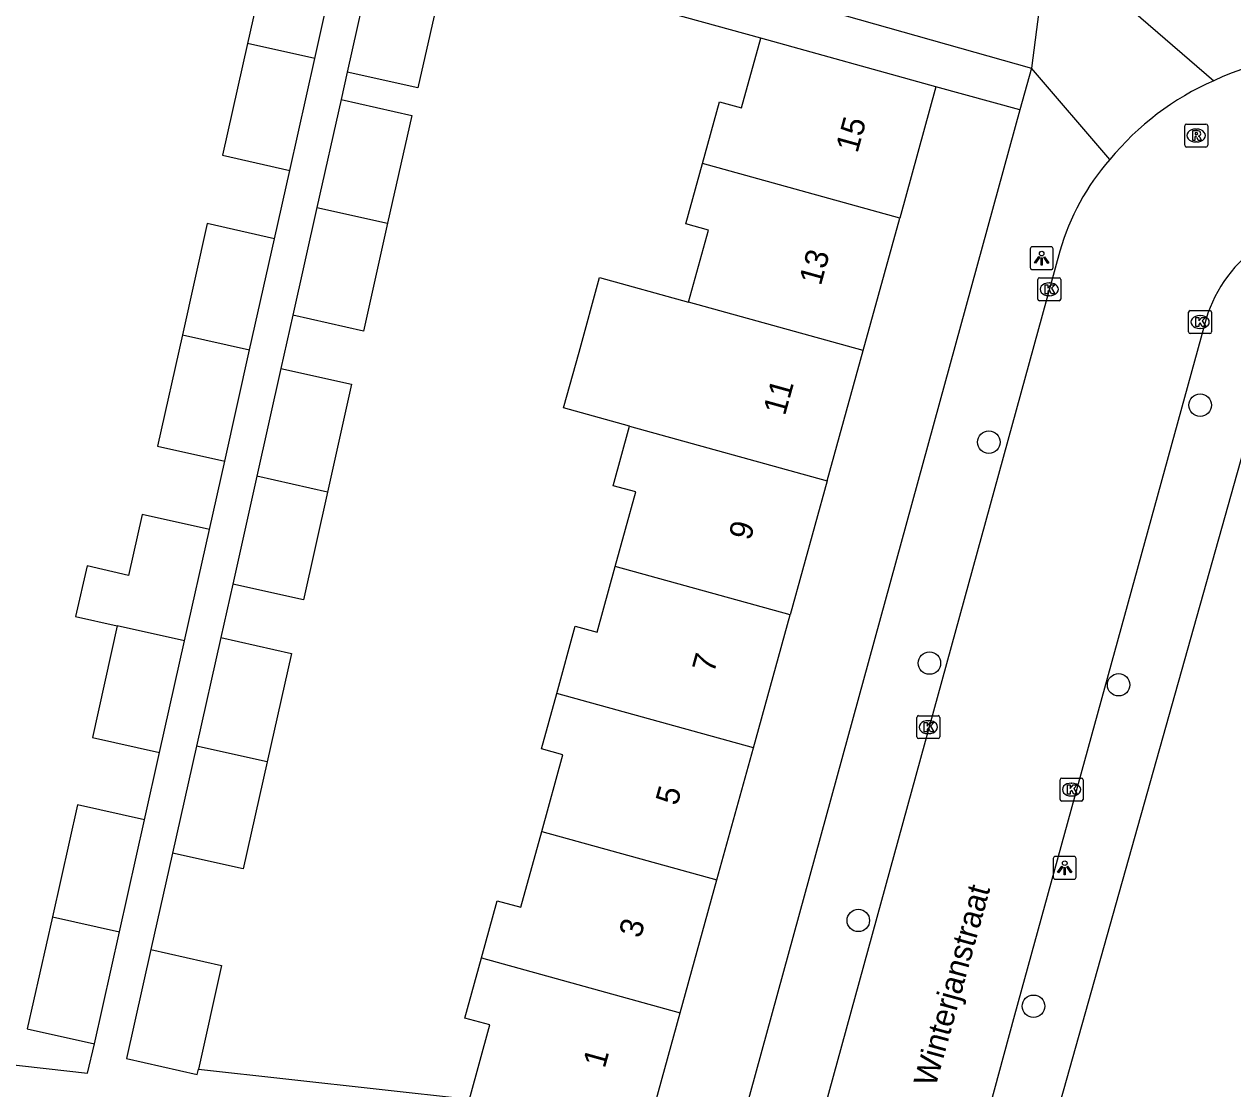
# Model space of a CAD drawing. Extents: x 162026 to 163499, y 387297 to 388169.
# Drawn here: x 162314.8 to 162367.4, y 387700.6 to 387747 of the extents above; entities that cross this region are included whole.
import ezdxf

# ---------------------------------------------------------------- set-up
doc = ezdxf.new("R2010")
doc.units = 0
for name, color, linetype in [('IMGEO_Boom', 7, 'Continuous'), ('IMGEO_Kolk', 7, 'Continuous'), ('IMGEO_Lichtpunt', 7, 'Continuous'), ('IMGEO_Openbare_ruimte_label', 7, 'Continuous'), ('IMGEO_Pand', 7, 'Continuous'), ('IMGEO_Pand_nummerreeks', 7, 'Continuous'), ('IMGEO_Rijbaan_lokaal_open', 7, 'Continuous'), ('IMGEO_Rioolput', 7, 'Continuous'), ('IMGEO_Voetpad_open', 7, 'Continuous')]:
    doc.layers.add(name, color=color, linetype=linetype)

msp = doc.modelspace()

# ---------------------------------------------------------------- linework, layer by layer
at = {"layer": 'IMGEO_Boom'}
for centre in [(162365.976, 387730.383), (162356.771, 387728.774), (162354.183, 387719.156), (162362.423, 387718.213), (162351.087, 387707.953), (162358.717, 387704.216)]:
    msp.add_circle(centre, 0.489, dxfattribs=at)
at = {"layer": 'IMGEO_Kolk'}
for p, q in [((162358.978, 387735.93), (162359.83, 387735.93)), ((162358.903, 387735.004), (162358.903, 387735.856)), ((162359.391, 387735.71), (162359.416, 387735.71)), ((162359.904, 387735.856), (162359.904, 387735.004)), ((162359.83, 387734.93), (162358.978, 387734.93)), ((162359.414, 387735.15), (162359.389, 387735.15)), ((162365.471, 387733.578), (162365.471, 387734.43)), ((162365.546, 387734.504), (162366.398, 387734.504)), ((162366.472, 387734.43), (162366.472, 387733.578)), ((162365.959, 387734.284), (162365.984, 387734.284)), ((162366.398, 387733.504), (162365.546, 387733.504)), ((162365.982, 387733.724), (162365.957, 387733.724)), ((162353.635, 387715.941), (162353.635, 387716.793)), ((162353.71, 387716.867), (162354.562, 387716.867)), ((162354.123, 387716.647), (162354.148, 387716.647)), ((162354.636, 387716.793), (162354.636, 387715.941)), ((162354.146, 387716.087), (162354.121, 387716.087)), ((162354.562, 387715.867), (162353.71, 387715.867)), ((162359.875, 387713.224), (162359.875, 387714.076)), ((162359.95, 387714.15), (162360.802, 387714.15)), ((162360.363, 387713.93), (162360.388, 387713.93)), ((162360.876, 387714.076), (162360.876, 387713.224)), ((162360.386, 387713.37), (162360.361, 387713.37)), ((162360.802, 387713.15), (162359.95, 387713.15))]:
    msp.add_line(p, q, dxfattribs=at)
for points in [[(162358.978, 387735.93), (162359.83, 387735.93)], [(162358.903, 387735.004), (162358.903, 387735.856)], [(162359.224, 387735.63), (162359.347, 387735.63), (162359.347, 387735.479), (162359.477, 387735.63), (162359.641, 387735.63), (162359.495, 387735.479), (162359.648, 387735.23), (162359.496, 387735.23), (162359.411, 387735.394), (162359.347, 387735.327), (162359.347, 387735.23), (162359.224, 387735.23), (162359.224, 387735.63)], [(162359.904, 387735.856), (162359.904, 387735.004)], [(162359.83, 387734.93), (162358.978, 387734.93)], [(162365.471, 387733.578), (162365.471, 387734.43)], [(162365.546, 387734.504), (162366.398, 387734.504)], [(162366.472, 387734.43), (162366.472, 387733.578)], [(162365.792, 387734.204), (162365.915, 387734.204), (162365.915, 387734.053), (162366.045, 387734.204), (162366.209, 387734.204), (162366.063, 387734.053), (162366.216, 387733.804), (162366.064, 387733.804), (162365.979, 387733.968), (162365.915, 387733.901), (162365.915, 387733.804), (162365.792, 387733.804), (162365.792, 387734.204)], [(162366.398, 387733.504), (162365.546, 387733.504)], [(162353.635, 387715.941), (162353.635, 387716.793)], [(162353.71, 387716.867), (162354.562, 387716.867)], [(162353.956, 387716.567), (162354.079, 387716.567), (162354.079, 387716.416), (162354.209, 387716.567), (162354.373, 387716.567), (162354.227, 387716.416), (162354.38, 387716.167), (162354.228, 387716.167), (162354.143, 387716.331), (162354.079, 387716.264), (162354.079, 387716.167), (162353.956, 387716.167), (162353.956, 387716.567)], [(162354.636, 387716.793), (162354.636, 387715.941)], [(162354.562, 387715.867), (162353.71, 387715.867)], [(162359.875, 387713.224), (162359.875, 387714.076)], [(162359.95, 387714.15), (162360.802, 387714.15)], [(162360.196, 387713.85), (162360.319, 387713.85), (162360.319, 387713.699), (162360.449, 387713.85), (162360.613, 387713.85), (162360.467, 387713.699), (162360.62, 387713.45), (162360.468, 387713.45), (162360.383, 387713.614), (162360.319, 387713.547), (162360.319, 387713.45), (162360.196, 387713.45), (162360.196, 387713.85)], [(162360.876, 387714.076), (162360.876, 387713.224)], [(162360.802, 387713.15), (162359.95, 387713.15)]]:
    msp.add_lwpolyline(points, dxfattribs=at)
for centre, start, end in [((162358.98, 387735.854), 91.552, 178.448), ((162358.98, 387735.854), 91.552, 178.448), ((162359.828, 387735.854), 1.552, 88.448), ((162359.828, 387735.854), 1.552, 88.448), ((162358.98, 387735.006), 181.552, 268.448), ((162358.98, 387735.006), 181.552, 268.448), ((162359.828, 387735.006), 271.552, 358.448), ((162359.828, 387735.006), 271.552, 358.448), ((162365.548, 387734.428), 91.552, 178.448), ((162365.548, 387734.428), 91.552, 178.448), ((162366.396, 387734.428), 1.552, 88.448), ((162366.396, 387734.428), 1.552, 88.448), ((162365.548, 387733.58), 181.552, 268.448), ((162365.548, 387733.58), 181.552, 268.448), ((162366.396, 387733.58), 271.552, 358.448), ((162366.396, 387733.58), 271.552, 358.448), ((162353.712, 387716.791), 91.552, 178.448), ((162353.712, 387716.791), 91.552, 178.448), ((162354.56, 387716.791), 1.552, 88.448), ((162354.56, 387716.791), 1.552, 88.448), ((162353.712, 387715.943), 181.552, 268.448), ((162353.712, 387715.943), 181.552, 268.448), ((162354.56, 387715.943), 271.552, 358.448), ((162354.56, 387715.943), 271.552, 358.448), ((162359.952, 387714.074), 91.552, 178.448), ((162359.952, 387714.074), 91.552, 178.448), ((162360.8, 387714.074), 1.552, 88.448), ((162360.8, 387714.074), 1.552, 88.448), ((162359.952, 387713.226), 181.552, 268.448), ((162359.952, 387713.226), 181.552, 268.448), ((162360.8, 387713.226), 271.552, 358.448), ((162360.8, 387713.226), 271.552, 358.448)]:
    msp.add_arc(centre, 0.0765, start, end, dxfattribs=at)
for centre, major_axis, ratio, start_param, end_param in [((162359.39, 387735.43), (-0.387, 0.002), 0.722429, 4.712389, 7.853982), ((162359.415, 387735.43), (-0.39, 0.002), 0.717154, 1.570796, 4.712389), ((162365.958, 387734.004), (-0.387, 0.002), 0.722429, 4.712389, 7.853982), ((162365.983, 387734.004), (-0.39, 0.002), 0.717154, 1.570796, 4.712389), ((162354.122, 387716.367), (-0.387, 0.002), 0.722429, 4.712389, 7.853982), ((162354.147, 387716.367), (-0.39, 0.002), 0.717154, 1.570796, 4.712389), ((162360.362, 387713.65), (-0.387, 0.002), 0.722429, 4.712389, 7.853982), ((162360.387, 387713.65), (-0.39, 0.002), 0.717154, 1.570796, 4.712389)]:
    msp.add_ellipse(centre, major_axis=major_axis, ratio=ratio, start_param=start_param, end_param=end_param, dxfattribs=at)
at = {"layer": 'IMGEO_Lichtpunt'}
for p, q in [((162358.574, 387737.186), (162358.574, 387736.379)), ((162358.574, 387737.186), (162358.574, 387736.379)), ((162359.476, 387737.281), (162358.668, 387737.281)), ((162359.476, 387737.281), (162358.668, 387737.281)), ((162359.57, 387736.379), (162359.57, 387737.186)), ((162359.57, 387736.379), (162359.57, 387737.186)), ((162358.668, 387736.285), (162359.476, 387736.285)), ((162358.668, 387736.285), (162359.476, 387736.285)), ((162360.479, 387710.742), (162359.671, 387710.742)), ((162360.479, 387710.742), (162359.671, 387710.742)), ((162359.577, 387710.647), (162359.577, 387709.84)), ((162359.577, 387710.647), (162359.577, 387709.84)), ((162360.573, 387709.84), (162360.573, 387710.647)), ((162360.573, 387709.84), (162360.573, 387710.647)), ((162359.671, 387709.746), (162360.479, 387709.746)), ((162359.671, 387709.746), (162360.479, 387709.746))]:
    msp.add_line(p, q, dxfattribs=at)
for points in [[(162358.948, 387736.85), (162358.987, 387736.822), (162358.799, 387736.56), (162358.761, 387736.587), (162358.948, 387736.85)], [(162359.05, 387736.802), (162359.097, 387736.802), (162359.097, 387736.48), (162359.05, 387736.48), (162359.05, 387736.802)], [(162359.16, 387736.822), (162359.198, 387736.849), (162359.385, 387736.587), (162359.346, 387736.559), (162359.16, 387736.822)], [(162359.951, 387710.311), (162359.99, 387710.283), (162359.802, 387710.021), (162359.764, 387710.048), (162359.951, 387710.311)], [(162360.053, 387710.263), (162360.1, 387710.263), (162360.1, 387709.941), (162360.053, 387709.941), (162360.053, 387710.263)], [(162360.163, 387710.283), (162360.201, 387710.31), (162360.388, 387710.048), (162360.349, 387710.02), (162360.163, 387710.283)]]:
    msp.add_lwpolyline(points, dxfattribs=at)
for centre in [(162359.073, 387736.984), (162360.076, 387710.445)]:
    msp.add_circle(centre, 0.0994, dxfattribs=at)
for centre, start, end in [((162358.668, 387737.186), 90, 180), ((162358.668, 387737.186), 90, 180), ((162359.476, 387737.186), 0, 90), ((162359.476, 387737.186), 0, 90), ((162358.668, 387736.379), 180, 270), ((162358.668, 387736.379), 180, 270), ((162359.476, 387736.379), 270, 0), ((162359.476, 387736.379), 270, 360), ((162359.671, 387710.647), 90, 180), ((162359.671, 387710.647), 90, 180), ((162360.479, 387710.647), 0, 90), ((162360.479, 387710.647), 0, 90), ((162359.671, 387709.84), 180, 270), ((162359.671, 387709.84), 180, 270), ((162360.479, 387709.84), 270, 0), ((162360.479, 387709.84), 270, 360)]:
    msp.add_arc(centre, 0.0946, start, end, dxfattribs=at)
at = {"layer": 'IMGEO_Pand'}
for points in [[(162328.215, 387750.384), (162325.568, 387750.976), (162324.484, 387746.126)], [(162327.412, 387745.471), (162328.496, 387750.321), (162328.215, 387750.384)], [(162332.743, 387748.993), (162329.887, 387749.632), (162328.825, 387744.884)], [(162332.743, 387748.993), (162332.971, 387748.943), (162331.908, 387744.194), (162328.825, 387744.884)], [(162324.484, 387746.126), (162323.397, 387741.262), (162326.324, 387740.607)], [(162327.412, 387745.471), (162324.484, 387746.126)], [(162344.294, 387740.906), (162345.037, 387743.597), (162346.006, 387743.329), (162346.842, 387746.355)], [(162354.469, 387744.249), (162346.842, 387746.355)], [(162326.324, 387740.607), (162327.412, 387745.471)], [(162354.469, 387744.249), (162352.89, 387738.531)], [(162328.558, 387743.692), (162327.508, 387738.995)], [(162328.558, 387743.692), (162331.641, 387743.002), (162330.589, 387738.306)], [(162343.692, 387734.868), (162344.56, 387738.01), (162343.569, 387738.283), (162344.294, 387740.906)], [(162352.89, 387738.531), (162344.294, 387740.906)], [(162327.508, 387738.995), (162326.458, 387734.301)], [(162327.508, 387738.995), (162330.589, 387738.306)], [(162325.659, 387737.632), (162322.731, 387738.287), (162321.648, 387733.442)], [(162330.589, 387738.306), (162329.538, 387733.613), (162326.458, 387734.301)], [(162351.298, 387732.767), (162352.89, 387738.531)], [(162324.576, 387732.787), (162325.659, 387737.632)], [(162341.12, 387729.469), (162338.251, 387730.262), (162338.923, 387732.697), (162339.818, 387735.938), (162343.692, 387734.868)], [(162351.298, 387732.767), (162343.692, 387734.868)], [(162321.648, 387733.442), (162320.565, 387728.595), (162323.492, 387727.94)], [(162321.648, 387733.442), (162324.576, 387732.787)], [(162323.492, 387727.94), (162324.576, 387732.787)], [(162349.729, 387727.09), (162351.298, 387732.767)], [(162325.941, 387731.988), (162324.89, 387727.291)], [(162325.941, 387731.988), (162329.02, 387731.299), (162327.968, 387726.602)], [(162340.5, 387723.357), (162341.397, 387726.605), (162340.405, 387726.879), (162341.12, 387729.469)], [(162341.12, 387729.469), (162349.729, 387727.09)], [(162324.89, 387727.291), (162323.84, 387722.597)], [(162327.968, 387726.602), (162324.89, 387727.291)], [(162349.729, 387727.09), (162348.117, 387721.253)], [(162327.968, 387726.602), (162326.917, 387721.908), (162323.84, 387722.597)], [(162322.829, 387724.975), (162319.901, 387725.629), (162319.307, 387722.971), (162317.506, 387723.384), (162317.001, 387721.18), (162318.816, 387720.774)], [(162321.744, 387720.119), (162322.829, 387724.975)], [(162337.952, 387717.83), (162338.761, 387720.76), (162339.71, 387720.498), (162340.5, 387723.357)], [(162348.117, 387721.253), (162340.5, 387723.357)], [(162346.518, 387715.464), (162348.117, 387721.253)], [(162318.816, 387720.774), (162317.73, 387715.915), (162320.657, 387715.26)], [(162321.744, 387720.119), (162318.816, 387720.774)], [(162323.319, 387720.267), (162322.262, 387715.541)], [(162323.319, 387720.267), (162326.396, 387719.579), (162325.338, 387714.853)], [(162320.657, 387715.26), (162321.744, 387720.119)], [(162337.299, 387711.824), (162338.221, 387715.162), (162337.286, 387715.42), (162337.952, 387717.83)], [(162346.518, 387715.464), (162337.952, 387717.83)], [(162322.262, 387715.541), (162321.221, 387710.886)], [(162325.338, 387714.853), (162322.262, 387715.541)], [(162344.93, 387709.716), (162346.518, 387715.464)], [(162325.338, 387714.853), (162324.295, 387710.198), (162321.221, 387710.886)], [(162320.002, 387712.331), (162317.075, 387712.986), (162315.986, 387708.116)], [(162318.914, 387707.461), (162320.002, 387712.331)], [(162334.671, 387706.319), (162335.359, 387708.809), (162336.388, 387708.525), (162337.299, 387711.824)], [(162337.299, 387711.824), (162344.93, 387709.716)], [(162343.331, 387703.927), (162344.93, 387709.716)], [(162315.986, 387708.116), (162314.895, 387703.235), (162317.822, 387702.58)], [(162315.986, 387708.116), (162318.914, 387707.461)], [(162317.822, 387702.58), (162318.914, 387707.461)], [(162320.281, 387706.684), (162319.221, 387701.941), (162322.29, 387701.241), (162322.344, 387701.485)], [(162320.281, 387706.684), (162323.355, 387705.997), (162322.344, 387701.485)], [(162334.152, 387700.171), (162335.045, 387703.401), (162333.949, 387703.704), (162334.671, 387706.319)], [(162334.671, 387706.319), (162343.331, 387703.927)], [(162341.717, 387698.082), (162343.331, 387703.927)]]:
    msp.add_lwpolyline(points, dxfattribs=at)
at = {"layer": 'IMGEO_Rijbaan_lokaal_open'}
for points in [[(162338.251, 387750.82), (162341.148, 387750), (162358.624, 387745.054)], [(162359.308, 387750.359), (162359.262, 387750), (162358.624, 387745.054)], [(162359.865, 387737.092), (162348.086, 387694.231), (162347.351, 387691.554), (162340.921, 387668.156), (162338.402, 387658.991)], [(162366.165, 387733.888), (162357.89, 387703.825), (162355.418, 387694.735)]]:
    msp.add_lwpolyline(points, dxfattribs=at)
for centre, radius, start, end in [((162371.746, 387733.469), 12.196, 82.5647, 115.1428), ((162371.474, 387733.333), 12.207, 113.7192, 140.5902), ((162369.705, 387734.312), 10.225, 138.5314, 164.2236), ((162371.859, 387732.467), 5.869, 125.3721, 165.9919)]:
    msp.add_arc(centre, radius, start, end, dxfattribs=at)
at = {"layer": 'IMGEO_Rioolput'}
for p, q in [((162365.301, 387741.698), (162365.301, 387742.55)), ((162365.376, 387742.624), (162366.228, 387742.624)), ((162365.789, 387742.404), (162365.814, 387742.404)), ((162366.302, 387742.55), (162366.302, 387741.698)), ((162365.812, 387741.844), (162365.787, 387741.844)), ((162366.228, 387741.624), (162365.376, 387741.624))]:
    msp.add_line(p, q, dxfattribs=at)
for points in [[(162365.301, 387741.698), (162365.301, 387742.55)], [(162365.376, 387742.624), (162366.228, 387742.624)], [(162365.89, 387742.322), (162365.638, 387742.324), (162365.638, 387741.924)], [(162365.816, 387742.243), (162365.762, 387742.243), (162365.762, 387742.162)], [(162366.302, 387742.55), (162366.302, 387741.698)], [(162365.638, 387741.924), (162365.762, 387741.924), (162365.762, 387742.086), (162365.773, 387742.086)], [(162365.762, 387742.162), (162365.814, 387742.162)], [(162365.82, 387742.057), (162365.891, 387741.924), (162366.031, 387741.924), (162365.966, 387742.05)], [(162366.228, 387741.624), (162365.376, 387741.624)]]:
    msp.add_lwpolyline(points, dxfattribs=at)
for centre, radius, start, end in [((162365.378, 387742.548), 0.0765, 91.552, 178.448), ((162365.378, 387742.548), 0.0765, 91.552, 178.448), ((162365.822, 387742.147), 0.0964, 77.0061, 93.1865), ((162365.836, 387742.204), 0.0378, 276.6634, 79.6772), ((162365.889, 387742.212), 0.109, 350.3612, 89.416), ((162366.226, 387742.548), 0.0765, 1.552, 88.448), ((162366.226, 387742.548), 0.0765, 1.552, 88.448), ((162365.772, 387742.033), 0.0533, 26.0293, 88.6989), ((162365.798, 387742.351), 0.19, 274.7715, 282.9687), ((162365.887, 387742.212), 0.112, 277.5842, 350.9817), ((162365.871, 387741.997), 0.108, 29.5134, 73.7905), ((162365.378, 387741.7), 0.0765, 181.552, 268.448), ((162365.378, 387741.7), 0.0765, 181.552, 268.448), ((162366.226, 387741.7), 0.0765, 271.552, 358.448), ((162366.226, 387741.7), 0.0765, 271.552, 358.448)]:
    msp.add_arc(centre, radius, start, end, dxfattribs=at)
for centre, major_axis, ratio, start_param, end_param in [((162365.788, 387742.124), (-0.387, 0.002), 0.722429, 4.712389, 7.853982), ((162365.813, 387742.124), (-0.39, 0.002), 0.717154, 1.570796, 4.712389)]:
    msp.add_ellipse(centre, major_axis=major_axis, ratio=ratio, start_param=start_param, end_param=end_param, dxfattribs=at)
at = {"layer": 'IMGEO_Voetpad_open'}
for points in [[(162359.868, 387750.298), (162360.213, 387750), (162366.564, 387744.509)], [(162346.842, 387746.355), (162336.587, 387749.187), (162332.873, 387749.575), (162332.743, 387748.993)], [(162328.825, 387744.884), (162328.558, 387743.692)], [(162358.624, 387745.054), (162358.126, 387743.239)], [(162362.043, 387741.083), (162358.624, 387745.054)], [(162358.126, 387743.239), (162354.469, 387744.249)], [(162358.126, 387743.239), (162345.447, 387697.053)], [(162325.659, 387737.632), (162326.324, 387740.607)], [(162326.458, 387734.301), (162325.941, 387731.988)], [(162388.85, 387687.545), (162360.613, 387690.79), (162360.527, 387690.801), (162360.284, 387690.849), (162360.046, 387690.917), (162359.815, 387691.007), (162359.593, 387691.117), (162359.382, 387691.247), (162359.183, 387691.394), (162358.998, 387691.559), (162358.829, 387691.74), (162358.676, 387691.935), (162358.542, 387692.143), (162358.427, 387692.362), (162358.331, 387692.591), (162358.257, 387692.827), (162358.204, 387693.069), (162358.172, 387693.315), (162358.163, 387693.562), (162358.176, 387693.81), (162358.211, 387694.055), (162358.268, 387694.296), (162369.363, 387733.695)], [(162322.829, 387724.975), (162323.492, 387727.94)], [(162323.84, 387722.597), (162323.319, 387720.267)], [(162320.002, 387712.331), (162320.657, 387715.26)], [(162321.221, 387710.886), (162320.281, 387706.684)], [(162304.508, 387702.775), (162317.518, 387701.302), (162317.822, 387702.58)], [(162322.344, 387701.485), (162334.152, 387700.171)]]:
    msp.add_lwpolyline(points, dxfattribs=at)

# ---------------------------------------------------------------- texts
at = {"layer": 'IMGEO_Openbare_ruimte_label'}
msp.add_text('Winterjanstraat', height=1, rotation=74.574, dxfattribs=at).set_placement((162354.444, 387700.667))
at = {"layer": 'IMGEO_Pand_nummerreeks'}
for s, rotation, p in [('15', 74.5591, (162351.047, 387741.326)), ('13', 74.5591, (162349.453, 387735.555)), ('11', 74.559, (162347.89, 387729.895)), ('9', 74.5591, (162346.388, 387724.457)), ('7', 74.5591, (162344.794, 387718.686)), ('5', 74.5591, (162343.2, 387712.915)), ('3', 74.5591, (162341.606, 387707.144)), ('1', 74.5591, (162340.042, 387701.484))]:
    msp.add_text(s, height=1, rotation=rotation, dxfattribs=at).set_placement(p)

doc.saveas('drawing.dxf')
